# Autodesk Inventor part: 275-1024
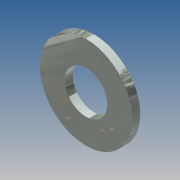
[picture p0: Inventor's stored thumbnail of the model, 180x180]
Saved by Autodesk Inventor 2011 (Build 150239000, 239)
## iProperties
Company: Autodesk Inc.
Created: 2010-06
Part Number: 275-1024
Document SubType Name: Modeling
Designer: Autodesk Inc.
Density: 1 g/cm^3
Catalog Web Link: http://www.vexrobotics.com/washers.html
Vendor: Innovation First, Inc.
Author: Autodesk Inc.
Title: VEX Robotics Kit of Parts
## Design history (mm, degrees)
sketch "Sketch1"
  geometry: C1 r 4.763 at (0, 0); 1 further point
  constraints: 1 centre point, 1 coincident
  dimensions: "d0" = 9.525 diameter of C1
extrude "Extrusion1" new body sketch "Sketch1" distance "d1" = 0.8128; taper "d2" = 0 deg
sketch "Sketch2"
  geometry: C1 r 4.763 at (0, 0) reference
hole "Hole1" sketch "Sketch2" at (0, 0) diameter "d3" = 4.3688; stored, may be unused: countersink angle "d7" = 82 deg, drill point angle "d9" = 118 deg; dims "d4" = 19.05, "d5" = 9.525, "d6" = 6.35, "d8" = 25.4
body "Solid1"
